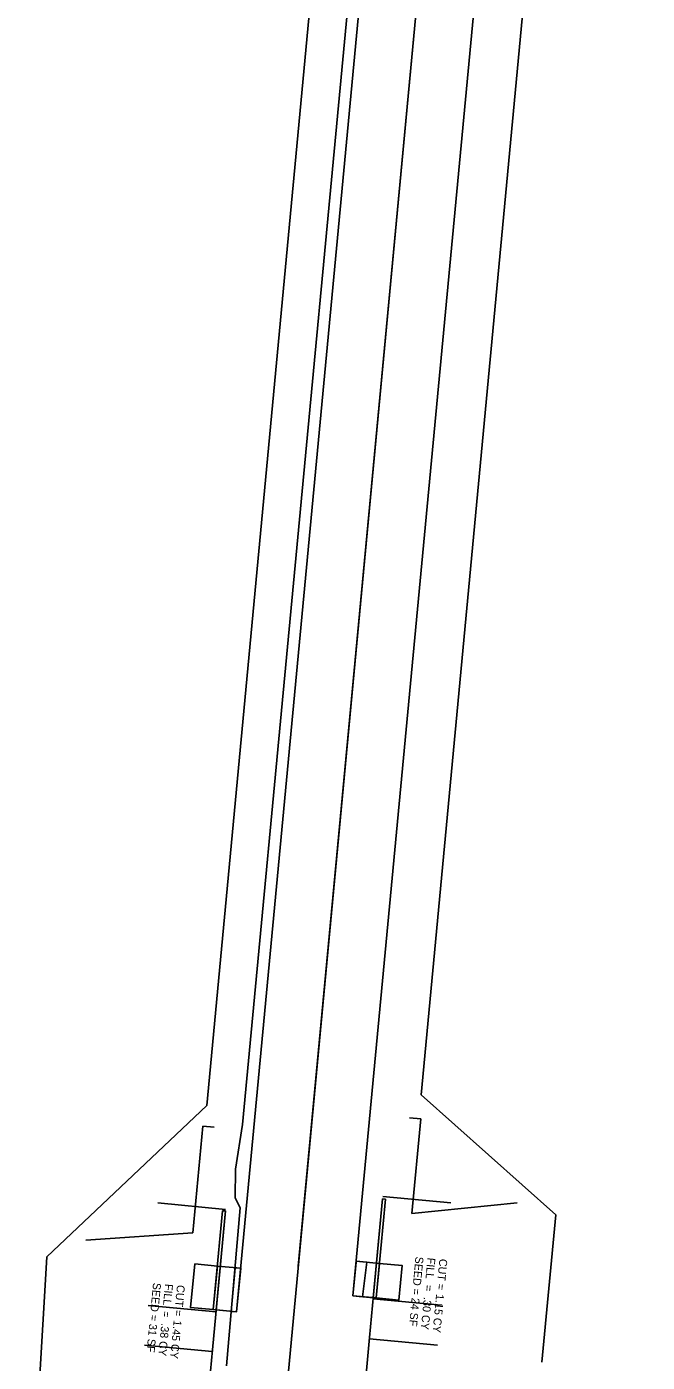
# Model space of a CAD drawing. Extents: x 1507088 to 1507206, y 518715 to 519811.
# Drawn here: x 1507089.1 to 1507197.7, y 519080.7 to 519314.3 of the extents above; entities that cross this region are included whole.
import ezdxf

# ---------------------------------------------------------------- set-up
doc = ezdxf.new("R2010")
doc.units = 0
for name, color, linetype in [('_CIVIL_CONSTRUCTION', 7, 'Continuous'), ('BR_P_Slab_Const_Joint', 7, 'Continuous'), ('BR_P_Slab_Object', 7, 'Continuous'), ('BR_X_Rail_Object', 7, 'Continuous'), ('BR_X_Sub_Foot_Hidden', 7, 'Continuous'), ('BR_X_Sub_Foot_Object', 7, 'Continuous'), ('BR_X_Sub_Object', 7, 'Continuous'), ('Default', 7, 'Continuous'), ('RW_X_CL', 7, 'Continuous'), ('RW_X_Esmt_SH', 7, 'Continuous'), ('RW_X_Fee_WL', 7, 'Continuous'), ('SC_Scratch2', 7, 'Continuous'), ('SV_P_Control_Cells_Set', 7, 'Continuous')]:
    doc.layers.add(name, color=color, linetype=linetype)

msp = doc.modelspace()

# ---------------------------------------------------------------- linework, layer by layer
at = {"layer": '_CIVIL_CONSTRUCTION'}
for p, q in [((1507149.75, 519092.01), (1507151.38, 519109.31)), ((1507151.88, 519109.27), (1507150.25, 519091.97)), ((1507151.37, 519109.31), (1507151.87, 519109.27)), ((1507121.76, 519089.93), (1507123.39, 519107.23)), ((1507123.89, 519107.18), (1507122.26, 519089.88)), ((1507123.39, 519107.23), (1507123.89, 519107.18)), ((1507150.25, 519091.97), (1507149.75, 519092.01)), ((1507122.26, 519089.88), (1507121.76, 519089.93))]:
    msp.add_line(p, q, dxfattribs=at)
at = {"layer": 'BR_P_Slab_Const_Joint'}
msp.add_line((1507168.11, 519432.6), (1507136.62, 519097.51), dxfattribs=at)
at = {"layer": 'BR_P_Slab_Object'}
for p, q in [((1507178.91, 519440.56), (1507146.18, 519092.35)), ((1507158.56, 519437.76), (1507125.83, 519089.55))]:
    msp.add_line(p, q, dxfattribs=at)
at = {"layer": 'BR_X_Rail_Object'}
for p, q in [((1507146.18, 519092.35), (1507149.75, 519092.01)), ((1507122.26, 519089.88), (1507125.83, 519089.55))]:
    msp.add_line(p, q, dxfattribs=at)
at = {"layer": 'BR_X_Sub_Foot_Hidden'}
for p, q in [((1507119.93, 519122.03), (1507118.17, 519103.37)), ((1507121.92, 519121.85), (1507119.93, 519122.03)), ((1507156.06, 519123.49), (1507158.05, 519123.3)), ((1507158.05, 519123.3), (1507156.49, 519106.74)), ((1507156.49, 519106.74), (1507174.91, 519108.59)), ((1507118.17, 519103.37), (1507099.44, 519102.1))]:
    msp.add_line(p, q, dxfattribs=at)
at = {"layer": 'BR_X_Sub_Foot_Object'}
for p, q in [((1507123.92, 519107.47), (1507112.04, 519108.59)), ((1507163.29, 519108.62), (1507151.41, 519109.74)), ((1507161.61, 519090.7), (1507149.73, 519091.82)), ((1507122.23, 519089.55), (1507110.35, 519090.67)), ((1507160.95, 519083.73), (1507149.08, 519084.85)), ((1507121.58, 519082.58), (1507109.7, 519083.7))]:
    msp.add_line(p, q, dxfattribs=at)
at = {"layer": 'BR_X_Sub_Object'}
msp.add_lwpolyline([(1507124.08, 519080.11), (1507126.46, 519107.76), (1507125.57, 519109.49), (1507125.65, 519114.5), (1507126.85, 519122.3), (1507153.61, 519406.42), (1507158.07, 519433.38), (1507161.5, 519464.79), (1507165.54, 519499.89), (1507169.61, 519537.99), (1507170.44, 519549.37), (1507169.66, 519552.48), (1507172.98, 519586.6), (1507174.76, 519590.96), (1507177.32, 519614.86), (1507180.87, 519647.04), (1507184.19, 519678.45), (1507187.3, 519710.95), (1507190.97, 519746.83), (1507194.45, 519778.56), (1507197.67, 519811.38)], dxfattribs=at)
at = {"layer": 'Default'}
for p, q in [((1507133.65, 519065.93), (1507166.4, 519414.4)), ((1507148.61, 519098.22), (1507147.88, 519092.19))]:
    msp.add_line(p, q, dxfattribs=at)
for points in [[(1507118.5, 519097.91), (1507122.48, 519097.54), (1507121.76, 519089.93), (1507117.78, 519090.3)], [(1507118.5, 519097.91), (1507122.48, 519097.54), (1507121.76, 519089.93), (1507117.78, 519090.3)], [(1507126.55, 519097.16), (1507125.83, 519089.55), (1507121.76, 519089.93), (1507122.48, 519097.54)], [(1507126.55, 519097.16), (1507125.83, 519089.55), (1507124.9, 519089.63), (1507125.56, 519097.25)], [(1507146.75, 519098.39), (1507148.61, 519098.22), (1507147.88, 519092.19), (1507146.18, 519092.35)], [(1507150.82, 519098.01), (1507150.25, 519091.97), (1507146.18, 519092.35), (1507146.75, 519098.39)], [(1507150.82, 519098.01), (1507154.8, 519097.63), (1507154.23, 519091.59), (1507150.25, 519091.97)], [(1507150.82, 519098.01), (1507154.8, 519097.63), (1507154.23, 519091.59), (1507150.25, 519091.97)]]:
    msp.add_lwpolyline(points, close=True, dxfattribs=at)
at = {"layer": 'RW_X_CL'}
for p, q in [((1507125.83, 519089.55), (1507126.51, 519096.83)), ((1507146.18, 519092.35), (1507146.73, 519098.2))]:
    msp.add_line(p, q, dxfattribs=at)
at = {"layer": 'RW_X_Esmt_SH'}
for p, q in [((1507146.61, 519402.35), (1507120.6, 519125.64)), ((1507184.04, 519403.45), (1507158.11, 519127.49)), ((1507158.11, 519127.49), (1507181.66, 519106.51)), ((1507092.63, 519099.16), (1507120.6, 519125.64)), ((1507181.66, 519106.51), (1507179.24, 519080.72)), ((1507089.12, 519039.54), (1507092.63, 519099.16))]:
    msp.add_line(p, q, dxfattribs=at)
at = {"layer": 'RW_X_Fee_WL'}
for p, q in [((1507123.89, 519107.18), (1507121.61, 519082.91)), ((1507121.61, 519082.91), (1507116.93, 519033.13))]:
    msp.add_line(p, q, dxfattribs=at)
at = {"layer": 'SV_P_Control_Cells_Set'}
for p, q in [((1507151.38, 519109.31), (1507149.1, 519085.04)), ((1507149.09, 519085.05), (1507140.91, 518997.93))]:
    msp.add_line(p, q, dxfattribs=at)

# ---------------------------------------------------------------- texts
at = {"layer": 'SC_Scratch2'}
for s, p in [('SEED = 24 SF', (1507157.14, 519099.25)), ('FILL  =  .30 CY', (1507159.23, 519099.06)), ('CUT =', (1507161.32, 519098.86)), ('SEED = 31 SF', (1507111.23, 519094.68)), ('FILL  =  .38 CY', (1507113.32, 519094.48)), ('CUT =', (1507115.41, 519094.29)), (' 1.15 CY', (1507160.79, 519093.21)), (' 1.45 CY', (1507114.88, 519088.64))]:
    msp.add_text(s, height=1.4, rotation=264.631, dxfattribs=at).set_placement(p)

doc.saveas('drawing.dxf')
